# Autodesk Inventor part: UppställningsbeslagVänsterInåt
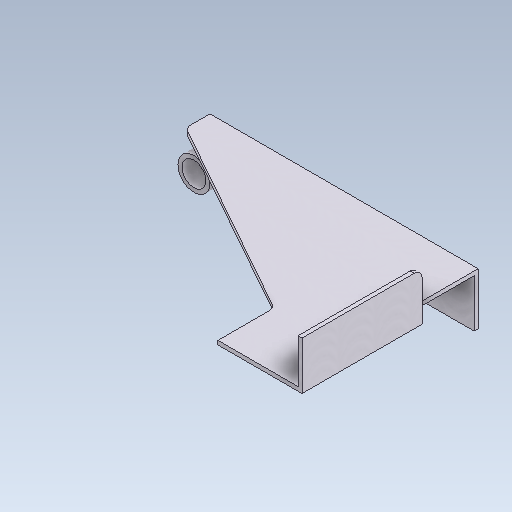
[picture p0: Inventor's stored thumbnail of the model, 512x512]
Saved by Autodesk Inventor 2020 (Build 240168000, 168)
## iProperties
Created: 2019-06
Part Number: UppställningsbeslagVänsterInåt
Material: Aluminum 6061, Welded
Document SubType Name: Modeling
Designer: cl
Density: 2.7 g/cm^3
Appearance: Weld - Aluminum
Author: cl
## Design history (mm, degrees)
sketch "Sketch1"
  geometry: L1 (0, 0)-(100, 0); L2 (100, 0)-(100, -70); L3 (100, -70)-(350, -210); L4 (350, -210)-(350, -240); L5 (350, -240)-(15, -240); L6 (15, -240)-(15, -150); L7 (15, -150)-(-5, -150); L8 (-5, -150)-(-5, 0); L9 (-5, 0)-(0, 0)
  constraints: 18 end point, 3 perpendicular, 3 vertical, 1 horizontal, 1 parallel
  dimensions: "d3" = 100 distance of L1.start L1.end; "d4" = 70 distance of L1.end L2.end; "d5" = 335 distance of L4.end L5.end; "d6" = 30 distance of L3.end L4.end; "d8" = 240 distance between parallel lines of L5 L1; "d9" = 90 distance of L5.end L6.end; "d10" = 20 distance of L6.end L7.end; "d11" = 350 distance from line of L4 L1.start
extrude "Extrusion1" new body sketch "Sketch1" distance "d12" = 5; taper "d13" = 0 deg
fillet "Fillet1" dims "d14" = 10
sketch "Sketch2"
  geometry: L1 (5, 150)-(-5, 150) reference; L2 (5, 150)-(0, 150); L3 (0, 150)-(0, 0); L4 (0, 0)-(5, 0); L5 (5, 0)-(5, 150); 1 further point
  constraints: 8 end point, 2 parallel, 1 horizontal, 1 perpendicular
extrude "Extrusion2" join sketch "Sketch2" distance "d15" = 55; taper "d16" = 0 deg
fillet "Fillet2" dims "d17" = 10
sketch "Sketch3"
  geometry: L1 (-15, -240)-(-350, -240) reference; L2 (-350, -240)-(-350, -215.861) reference; L3 (-15, -240)-(-350, -240); L4 (-350, -240)-(-350, -235); L5 (-350, -235)-(-15, -235); L6 (-15, -235)-(-15, -240); 2 further points
  constraints: 8 end point, 2 parallel, 1 horizontal, 1 perpendicular, 1 point on line
  dimensions: "d18" = 5 distance between parallel lines of L1 L5
extrude "Extrusion3" join sketch "Sketch3" distance "d19" = 60; taper "d20" = 0 deg
sketch "Sketch4"
  geometry: L1 (0, 0)-(0, -60) reference; L2 (335, -60)-(0, -60) reference; C1 r 20 at (20, -30); C2 r 15 at (20, -30); 1 further point
  constraints: 2 centre point, 1 coincident, 1 tangent
  dimensions: "d21" = 40 diameter of C1; "d22" = 30 diameter of C2; "d23" = 30 distance from line of L2 C1.centre
extrude "Extrusion4" join sketch "Sketch4" distance "d24" = 35; taper "d25" = 0 deg
body "Solid1"
